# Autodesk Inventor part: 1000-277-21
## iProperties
Created: 2007-03
Part Number: 1000-277-21
Document SubType Name: Modeling
Designer: Andy Moles
Material: Steel
Mass: 12.7834 g
Surface Area: 13.9754 cm^2
Volume: 1.62846 cm^3
Density: 7.85 g/cm^3
Author: Andy Moles
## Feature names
1. Base1
